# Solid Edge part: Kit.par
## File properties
Sűrűség: 0,000 kg/m^3
Pontosság: 0,990
Author: bmolnar
Last saved by: psaghy
Revision: 77
Username: bmolnar
Dokumentum tartalom típus: 0
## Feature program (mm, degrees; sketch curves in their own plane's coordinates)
base feature "unnamed BaseFeature 1"
sketch for "Furat_1" plane through (0, 0, 48.5) normal (0, 0, 1) x-axis (0.707107, -0.707107, 0)
  hole centre (0, 62.9325) bore radius 4.188
hole "Furat_1" nominal diameter 10 finite  VBottomAngle = 118 deg; ThreadDepth = 17 mm
sketch for "unnamed Hole 1" plane through (0, 0, 48.5) normal (0, 0, 1) x-axis (0.707107, -0.707107, 0)
  hole centre (-62.9325, 0) bore radius 4.188
hole "unnamed Hole 1" finite
sketch for "unnamed Hole 2" plane through (0, 0, 48.5) normal (0, 0, 1) x-axis (0.707107, -0.707107, 0)
  hole centre (0, -62.9325) bore radius 4.188
hole "unnamed Hole 2" finite
sketch for "unnamed Hole 3" plane through (0, 0, 48.5) normal (0, 0, 1) x-axis (0.707107, -0.707107, 0)
  hole centre (62.9325, 0) bore radius 4.188
hole "unnamed Hole 3" finite
pattern "unnamed Pattern 1" of "Furat_1", "unnamed Hole 1", "unnamed Hole 2", "unnamed Hole 3"
sketch for "Furat_5" plane through (55, -0.0046, 26.9988) normal (1, 0, 0) x-axis (0, 0, -1)
hole "Furat_5" diameter 20.955 finite  ThreadDepth = 25 mm
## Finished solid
Body 1: solid body, 559 faces, 1278 edges, 785 vertices, 8 internal voids.
  Faces by surface: cylinder 177, plane 162, cone 67, sphere 54, torus 53, spline 28, swept 18
  Edges by curve: circle 445, curve on surface 410, line 379, spline 40, ellipse 4
Bounding box of the edges (mm; curved faces can reach further): 110.000 x 110.000 x 78.500, from (-55, -55, 8) to (55, 55, 86.5).
Cylindrical faces by radius (mm): R0.3906 x2, R0.436 x1, R0.4566 x1, R0.5319 x1, R0.6854 x2, R0.701 x1, R0.7273 x1, R0.7952 x1, R0.8489 x1, R0.9223 x1, R1 x31, R1.0003 x1, R1.0017 x8, R1.1393 x1, R1.2532 x1, R1.2992 x1, R1.3173 x1, R1.3418 x1, R1.3734 x1, R1.4839 x1, R1.5702 x1, R1.5902 x3, R1.7026 x2, R1.7139 x2, R1.8341 x1, R2 x12, R2.0009 x12, R2.003 x12, R2.0038 x6, R2.0039 x6, R2.1429 x2, R2.1983 x1, R2.95 x1, R4.188 x8, R5 x4, R5.15 x4, R6 x1, R8 x4, R8.15 x4, R8.5 x2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
Conical faces (half-angle, radius in mm at the cone's reference point): 0.0014 deg R1.001 x6, 1 deg R24.75 x6, 1 deg R44 x6, 1.6538 deg R14.25 x1, 3.5477 deg R15.2454 x1, 5.1705 deg R12.9 x1, 8.3742 deg R12.5032 x1, 13.2989 deg R13.6846 x1, 14.7738 deg R13.2787 x1, 15 deg R25.1732 x1, 25.0169 deg R16.81 x1, 30 deg R6.1443 x1, 30 deg R14.8557 x2, 30 deg R15.1443 x1, 30 deg R26.75 x1, 43.4089 deg R46.25 x1, 45 deg R3.75 x1, 45 deg R3.875 x1, 45 deg R5.3 x8, 45 deg R7.85 x8, 45 deg R10.91 x1, 45 deg R12.65 x2, 45 deg R17.85 x1, 47.9357 deg R39.7887 x6, 47.9357 deg R47.75 x3, 59 deg R4.188 x4
Toroidal faces (ring radius, tube radius in mm): R5.3 r0.3 x4, R5.7 r0.3 x1, R7.95 r0.2 x4, R8.65 r0.5 x4, R11.5 r1 x2, R12.8 r0.3 x1, R12.8088 r0.3 x1, R13.9279 r0.25 x1, R14.7464 r0.5 x1, R15.5 r1 x1, R17.3 r0.2 x1, R23 r3 x1, R23.4827 r1 x1, R26.7154 r2 x6, R28 r0.5 x1, R34.8084 r2 x6, R42.0155 r2 x6, R53 r1 x3, R55.4306 r1 x2, R57 r1 x6
Spherical faces by radius (mm): R1 x18, R2 x36
Planar faces by outward normal: +x 21, +y 11, +z 37, -x 1, -y 10, -z 25, oblique 57
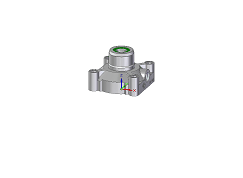
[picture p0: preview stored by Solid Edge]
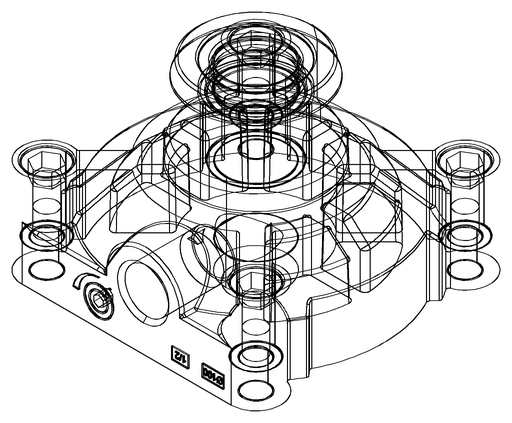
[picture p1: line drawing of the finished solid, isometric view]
